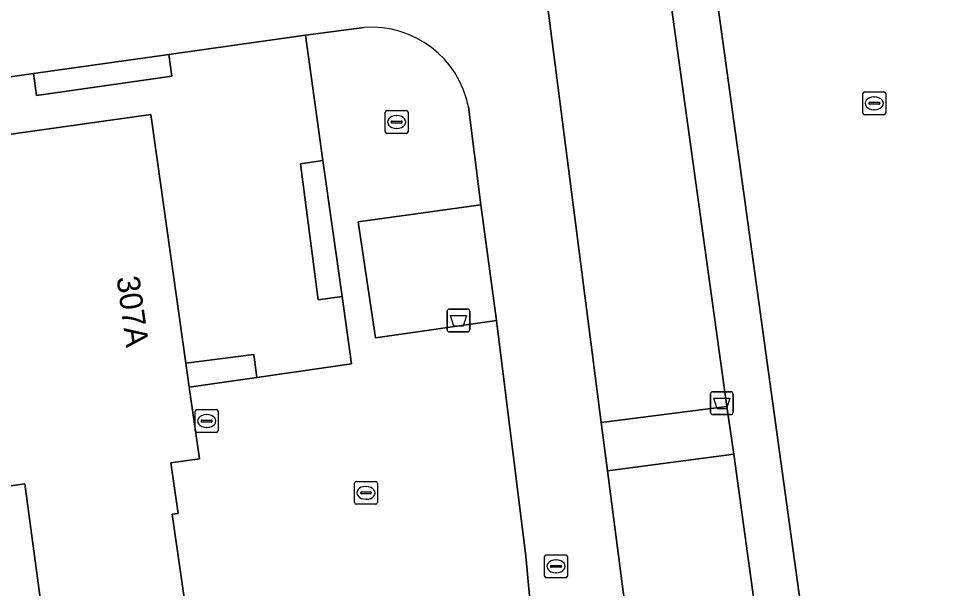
# Model space of a CAD drawing. Extents: x 162156 to 163172, y 378995 to 380779.
# Drawn here: x 162268.76 to 162309.86, y 379918.76 to 379943.7 of the extents above; entities that cross this region are included whole.
import ezdxf

# ---------------------------------------------------------------- set-up
doc = ezdxf.new("R2010")
doc.units = 0
for name, color, linetype in [('IMGEO_Afvalbak', 7, 'Continuous'), ('IMGEO_Brandkraan', 7, 'Continuous'), ('IMGEO_Groenvoorziening', 7, 'Continuous'), ('IMGEO_Kolk', 7, 'Continuous'), ('IMGEO_Pand', 7, 'Continuous'), ('IMGEO_Pand_nummerreeks', 7, 'Continuous'), ('IMGEO_Rioolput', 7, 'Continuous'), ('IMGEO_Terreindeel_open', 7, 'Continuous'), ('IMGEO_Voetpad_open', 7, 'Continuous'), ('IMGEO_Waterleidingput', 7, 'Continuous')]:
    doc.layers.add(name, color=color, linetype=linetype)

msp = doc.modelspace()

# ---------------------------------------------------------------- linework, layer by layer
at = {"layer": 'IMGEO_Afvalbak'}
for p, q in [((162287.621, 379930.992), (162288.411, 379930.992)), ((162288.411, 379930.992), (162287.621, 379930.992)), ((162287.521, 379930.092), (162287.521, 379930.892)), ((162287.521, 379930.892), (162287.521, 379930.092)), ((162288.511, 379930.892), (162288.511, 379930.092)), ((162288.511, 379930.092), (162288.511, 379930.892)), ((162288.411, 379929.992), (162287.621, 379929.992)), ((162287.621, 379929.992), (162288.411, 379929.992)), ((162299.153, 379927.37), (162299.943, 379927.37)), ((162299.943, 379927.37), (162299.153, 379927.37)), ((162299.053, 379926.47), (162299.053, 379927.27)), ((162299.053, 379927.27), (162299.053, 379926.47)), ((162300.043, 379927.27), (162300.043, 379926.47)), ((162300.043, 379926.47), (162300.043, 379927.27)), ((162299.943, 379926.37), (162299.153, 379926.37)), ((162299.153, 379926.37), (162299.943, 379926.37))]:
    msp.add_line(p, q, dxfattribs=at)
for points in [[(162287.664, 379930.706), (162288.368, 379930.706), (162288.219, 379930.236), (162287.813, 379930.236), (162287.664, 379930.706)], [(162299.196, 379927.084), (162299.9, 379927.084), (162299.751, 379926.614), (162299.345, 379926.614), (162299.196, 379927.084)]]:
    msp.add_lwpolyline(points, dxfattribs=at)
for centre, start, end in [((162287.621, 379930.892), 90, 180), ((162287.621, 379930.892), 90, 180), ((162288.411, 379930.892), 0, 90), ((162288.411, 379930.892), 360, 90), ((162287.621, 379930.092), 180, 270), ((162287.621, 379930.092), 180, 270), ((162288.411, 379930.092), 270, 0), ((162288.411, 379930.092), 270, 0), ((162299.153, 379927.27), 90, 180), ((162299.153, 379927.27), 90, 180), ((162299.943, 379927.27), 0, 90), ((162299.943, 379927.27), 360, 90), ((162299.153, 379926.47), 180, 270), ((162299.153, 379926.47), 180, 270), ((162299.943, 379926.47), 270, 0), ((162299.943, 379926.47), 270, 0)]:
    msp.add_arc(centre, 0.1, start, end, dxfattribs=at)
at = {"layer": 'IMGEO_Brandkraan'}
for p, q in [((162276.491, 379925.66), (162276.491, 379926.512)), ((162276.566, 379926.586), (162277.418, 379926.586)), ((162277.492, 379926.512), (162277.492, 379925.66)), ((162276.75, 379926.08), (162276.75, 379926.092)), ((162277.188, 379926.043), (162276.79, 379926.043)), ((162276.793, 379926.129), (162277.191, 379926.129)), ((162276.979, 379926.366), (162277.004, 379926.366)), ((162277.234, 379926.092), (162277.234, 379926.08)), ((162277.002, 379925.806), (162276.977, 379925.806)), ((162277.418, 379925.586), (162276.566, 379925.586))]:
    msp.add_line(p, q, dxfattribs=at)
for points in [[(162276.491, 379925.66), (162276.491, 379926.512)], [(162276.566, 379926.586), (162277.418, 379926.586)], [(162277.492, 379926.512), (162277.492, 379925.66)], [(162277.418, 379925.586), (162276.566, 379925.586)]]:
    msp.add_lwpolyline(points, dxfattribs=at)
for centre, radius, start, end in [((162276.568, 379926.51), 0.0765, 91.552, 178.448), ((162276.568, 379926.51), 0.0765, 91.552, 178.448), ((162277.416, 379926.51), 0.0765, 1.552, 88.448), ((162277.416, 379926.51), 0.0765, 1.552, 88.448), ((162276.79, 379926.089), 0.0403, 85.8775, 175.7526), ((162276.787, 379926.079), 0.0366, 178.938, 274.7102), ((162277.191, 379926.086), 0.043, 264.8664, 352.4533), ((162277.195, 379926.091), 0.0386, 1.7309, 96.639), ((162276.568, 379925.662), 0.0765, 181.552, 268.448), ((162276.568, 379925.662), 0.0765, 181.552, 268.448), ((162277.416, 379925.662), 0.0765, 271.552, 358.448), ((162277.416, 379925.662), 0.0765, 271.552, 358.448)]:
    msp.add_arc(centre, radius, start, end, dxfattribs=at)
for centre, major_axis, ratio, start_param, end_param in [((162276.978, 379926.086), (-0.387, 0.002), 0.722429, 4.712389, 7.853982), ((162277.003, 379926.086), (-0.39, 0.002), 0.717154, 1.570796, 4.712389)]:
    msp.add_ellipse(centre, major_axis=major_axis, ratio=ratio, start_param=start_param, end_param=end_param, dxfattribs=at)
at = {"layer": 'IMGEO_Groenvoorziening'}
for points in [[(162297.268, 379944.856), (162291.938, 379944.183), (162294.275, 379926.021), (162299.766, 379926.723)], [(162275.328, 379942.144), (162269.407, 379941.31), (162269.531, 379940.346), (162275.471, 379941.196)], [(162282.084, 379937.493), (162281.102, 379937.348), (162281.874, 379931.397), (162282.92, 379931.544)], [(162289.001, 379935.557), (162283.618, 379934.81), (162284.388, 379929.728), (162289.689, 379930.495)], [(162276.082, 379928.614), (162276.229, 379927.573), (162279.187, 379927.996), (162279.054, 379929.003)], [(162300.075, 379924.63), (162294.55, 379923.905), (162297.816, 379898.725), (162303.536, 379899.484)]]:
    msp.add_lwpolyline(points, close=True, dxfattribs=at)
at = {"layer": 'IMGEO_Kolk'}
for p, q in [((162284.811, 379938.756), (162284.811, 379939.608)), ((162284.886, 379939.682), (162285.738, 379939.682)), ((162285.812, 379939.608), (162285.812, 379938.756)), ((162285.113, 379939.225), (162285.511, 379939.225)), ((162285.299, 379939.462), (162285.324, 379939.462)), ((162285.07, 379939.176), (162285.07, 379939.188)), ((162285.508, 379939.139), (162285.11, 379939.139)), ((162285.322, 379938.902), (162285.297, 379938.902)), ((162285.554, 379939.188), (162285.554, 379939.176)), ((162285.738, 379938.682), (162284.886, 379938.682)), ((162283.468, 379922.515), (162283.468, 379923.367)), ((162283.543, 379923.441), (162284.395, 379923.441)), ((162283.956, 379923.221), (162283.981, 379923.221)), ((162284.469, 379923.367), (162284.469, 379922.515)), ((162283.727, 379922.935), (162283.727, 379922.947)), ((162284.165, 379922.898), (162283.767, 379922.898)), ((162283.77, 379922.984), (162284.168, 379922.984)), ((162284.211, 379922.947), (162284.211, 379922.935)), ((162284.395, 379922.441), (162283.543, 379922.441)), ((162283.979, 379922.661), (162283.954, 379922.661))]:
    msp.add_line(p, q, dxfattribs=at)
for points in [[(162284.811, 379938.756), (162284.811, 379939.608)], [(162284.886, 379939.682), (162285.738, 379939.682)], [(162285.812, 379939.608), (162285.812, 379938.756)], [(162285.738, 379938.682), (162284.886, 379938.682)], [(162283.468, 379922.515), (162283.468, 379923.367)], [(162283.543, 379923.441), (162284.395, 379923.441)], [(162284.469, 379923.367), (162284.469, 379922.515)], [(162284.395, 379922.441), (162283.543, 379922.441)]]:
    msp.add_lwpolyline(points, dxfattribs=at)
for centre, radius, start, end in [((162284.888, 379939.606), 0.0765, 91.552, 178.448), ((162284.888, 379939.606), 0.0765, 91.552, 178.448), ((162285.736, 379939.606), 0.0765, 1.552, 88.448), ((162285.736, 379939.606), 0.0765, 1.552, 88.448), ((162285.11, 379939.185), 0.0403, 85.8775, 175.7526), ((162285.515, 379939.187), 0.0386, 1.7309, 96.639), ((162285.107, 379939.175), 0.0366, 178.938, 274.7102), ((162285.511, 379939.182), 0.043, 264.8664, 352.4533), ((162284.888, 379938.758), 0.0765, 181.552, 268.448), ((162284.888, 379938.758), 0.0765, 181.552, 268.448), ((162285.736, 379938.758), 0.0765, 271.552, 358.448), ((162285.736, 379938.758), 0.0765, 271.552, 358.448), ((162283.545, 379923.365), 0.0765, 91.552, 178.448), ((162283.545, 379923.365), 0.0765, 91.552, 178.448), ((162284.393, 379923.365), 0.0765, 1.552, 88.448), ((162284.393, 379923.365), 0.0765, 1.552, 88.448), ((162283.767, 379922.944), 0.0403, 85.8775, 175.7526), ((162283.764, 379922.934), 0.0366, 178.938, 274.7102), ((162284.168, 379922.941), 0.043, 264.8664, 352.4533), ((162284.172, 379922.946), 0.0386, 1.7309, 96.639), ((162283.545, 379922.517), 0.0765, 181.552, 268.448), ((162283.545, 379922.517), 0.0765, 181.552, 268.448), ((162284.393, 379922.517), 0.0765, 271.552, 358.448), ((162284.393, 379922.517), 0.0765, 271.552, 358.448)]:
    msp.add_arc(centre, radius, start, end, dxfattribs=at)
for centre, major_axis, ratio, start_param, end_param in [((162285.298, 379939.182), (-0.387, 0.002), 0.722429, 4.712389, 7.853982), ((162285.323, 379939.182), (-0.39, 0.002), 0.717154, 1.570796, 4.712389), ((162283.955, 379922.941), (-0.387, 0.002), 0.722429, 4.712389, 7.853982), ((162283.98, 379922.941), (-0.39, 0.002), 0.717154, 1.570796, 4.712389)]:
    msp.add_ellipse(centre, major_axis=major_axis, ratio=ratio, start_param=start_param, end_param=end_param, dxfattribs=at)
at = {"layer": 'IMGEO_Pand'}
msp.add_lwpolyline([(162276.229, 379927.573), (162276.082, 379928.614), (162274.545, 379939.509), (162264.468, 379938.097), (162264.462, 379938.136), (162261.421, 379937.699), (162261.387, 379937.936), (162260.516, 379937.807), (162261.083, 379933.902), (162262.057, 379927.197), (162262.913, 379927.322), (162262.877, 379927.566), (162265.84, 379927.99), (162266.556, 379922.984), (162266.589, 379922.989), (162269.032, 379923.34), (162270.077, 379915.508), (162276.289, 379916.315), (162275.482, 379922.006), (162275.739, 379922.042), (162275.426, 379924.249), (162276.673, 379924.426)], close=True, dxfattribs=at)
at = {"layer": 'IMGEO_Rioolput'}
for p, q in [((162291.79, 379919.297), (162291.79, 379920.149)), ((162291.865, 379920.223), (162292.717, 379920.223)), ((162292.278, 379920.003), (162292.303, 379920.003)), ((162292.791, 379920.149), (162292.791, 379919.297)), ((162292.049, 379919.717), (162292.049, 379919.729)), ((162292.487, 379919.68), (162292.089, 379919.68)), ((162292.092, 379919.766), (162292.49, 379919.766)), ((162292.533, 379919.729), (162292.533, 379919.717)), ((162292.717, 379919.223), (162291.865, 379919.223)), ((162292.301, 379919.443), (162292.276, 379919.443))]:
    msp.add_line(p, q, dxfattribs=at)
for points in [[(162291.79, 379919.297), (162291.79, 379920.149)], [(162291.865, 379920.223), (162292.717, 379920.223)], [(162292.791, 379920.149), (162292.791, 379919.297)], [(162292.717, 379919.223), (162291.865, 379919.223)]]:
    msp.add_lwpolyline(points, dxfattribs=at)
for centre, radius, start, end in [((162291.867, 379920.147), 0.0765, 91.552, 178.448), ((162291.867, 379920.147), 0.0765, 91.552, 178.448), ((162292.715, 379920.147), 0.0765, 1.552, 88.448), ((162292.715, 379920.147), 0.0765, 1.552, 88.448), ((162292.089, 379919.726), 0.0403, 85.8775, 175.7526), ((162292.086, 379919.716), 0.0366, 178.938, 274.7102), ((162292.49, 379919.723), 0.043, 264.8664, 352.4533), ((162292.494, 379919.728), 0.0386, 1.7309, 96.639), ((162291.867, 379919.299), 0.0765, 181.552, 268.448), ((162291.867, 379919.299), 0.0765, 181.552, 268.448), ((162292.715, 379919.299), 0.0765, 271.552, 358.448), ((162292.715, 379919.299), 0.0765, 271.552, 358.448)]:
    msp.add_arc(centre, radius, start, end, dxfattribs=at)
for centre, major_axis, ratio, start_param, end_param in [((162292.277, 379919.723), (-0.387, 0.002), 0.722429, 4.712389, 7.853982), ((162292.302, 379919.723), (-0.39, 0.002), 0.717154, 1.570796, 4.712389)]:
    msp.add_ellipse(centre, major_axis=major_axis, ratio=ratio, start_param=start_param, end_param=end_param, dxfattribs=at)
at = {"layer": 'IMGEO_Terreindeel_open'}
msp.add_lwpolyline([(162369.608, 379954.625), (162368.912, 379959.951), (162298.57, 379950.126), (162313.201, 379844.187), (162383.496, 379853.919)], close=True, dxfattribs=at)
at = {"layer": 'IMGEO_Voetpad_open'}
for points in [[(162258.604, 379948.382), (162258.531, 379948.938), (162251.352, 380003.968), (162249.679, 380016.96), (162245.315, 380016.372), (162245.197, 380016.361), (162246.876, 380003.284), (162254.966, 379941.182), (162255.213, 379939.286), (162260.444, 379940.048), (162266.413, 379940.889), (162269.407, 379941.31), (162275.328, 379942.144), (162281.312, 379942.987), (162283.887, 379943.326)], [(162298.076, 379896.625), (162297.816, 379898.725), (162294.55, 379923.905), (162294.275, 379926.021), (162291.938, 379944.183), (162291.356, 379948.604), (162289.52, 379948.334), (162264.168, 379944.746), (162263.207, 379944.595)], [(162283.887, 379943.326), (162281.312, 379942.987), (162282.084, 379937.493), (162282.92, 379931.544), (162283.335, 379928.593), (162279.187, 379927.996), (162276.229, 379927.573), (162276.673, 379924.426), (162275.426, 379924.249), (162275.739, 379922.042), (162275.482, 379922.006), (162276.289, 379916.315), (162290.259, 379918.129), (162291.138, 379918.277), (162290.973, 379920.171), (162289.689, 379930.495)], [(162264.468, 379938.097), (162274.545, 379939.509), (162276.082, 379928.614), (162279.054, 379929.003), (162279.187, 379927.996), (162283.335, 379928.593), (162282.92, 379931.544), (162281.874, 379931.397), (162281.102, 379937.348), (162282.084, 379937.493), (162281.312, 379942.987), (162275.328, 379942.144), (162275.471, 379941.196), (162269.531, 379940.346), (162269.407, 379941.31), (162266.413, 379940.889)], [(162289.689, 379930.495), (162284.388, 379929.728), (162283.618, 379934.81), (162289.001, 379935.557), (162288.46, 379939.846)], [(162288.46, 379939.846), (162289.001, 379935.557), (162289.689, 379930.495), (162290.973, 379920.171), (162291.138, 379918.277), (162293.851, 379898.324), (162292.836, 379898.197), (162293.23, 379895.146), (162294.23, 379895.292), (162295.384, 379886.281), (162295.69, 379884.185), (162295.989, 379881.868), (162298.282, 379864.121), (162300.383, 379864.471), (162302.148, 379864.765), (162301.698, 379868.289), (162298.076, 379896.625)], [(162270.077, 379915.508), (162269.032, 379923.34), (162266.589, 379922.989)]]:
    msp.add_lwpolyline(points, dxfattribs=at)
for points in [[(162369.639, 379962.54), (162342.462, 379958.776), (162315.523, 379955.046), (162296.268, 379952.379), (162296.65, 379949.341), (162297.268, 379944.856), (162299.766, 379926.723), (162300.075, 379924.63), (162303.536, 379899.484), (162303.845, 379897.389), (162309.019, 379859.894), (162311.244, 379843.757), (162311.908, 379838.939), (162341.724, 379843.061), (162341.312, 379846.043), (162383.131, 379851.844), (162384.777, 379852.072), (162370.627, 379954.755)], [(162368.912, 379959.951), (162369.608, 379954.625), (162383.496, 379853.919), (162313.201, 379844.187), (162298.57, 379950.126)], [(162299.766, 379926.723), (162294.275, 379926.021), (162294.55, 379923.905), (162300.075, 379924.63)]]:
    msp.add_lwpolyline(points, close=True, dxfattribs=at)
msp.add_arc((162284.196, 379938.987), 4.35, 11.3888, 94.0697, dxfattribs=at)
msp.add_arc((162284.196, 379938.987), 4.35, 11.3888, 94.0697, dxfattribs=at)
at = {"layer": 'IMGEO_Waterleidingput'}
for p, q in [((162305.728, 379939.576), (162305.728, 379940.428)), ((162305.803, 379940.502), (162306.655, 379940.502)), ((162306.729, 379940.428), (162306.729, 379939.576)), ((162306.03, 379940.045), (162306.428, 379940.045)), ((162306.216, 379940.282), (162306.241, 379940.282)), ((162305.987, 379939.996), (162305.987, 379940.008)), ((162306.425, 379939.959), (162306.027, 379939.959)), ((162306.239, 379939.722), (162306.214, 379939.722)), ((162306.471, 379940.008), (162306.471, 379939.996)), ((162306.655, 379939.502), (162305.803, 379939.502))]:
    msp.add_line(p, q, dxfattribs=at)
for points in [[(162305.728, 379939.576), (162305.728, 379940.428)], [(162305.803, 379940.502), (162306.655, 379940.502)], [(162306.729, 379940.428), (162306.729, 379939.576)], [(162306.655, 379939.502), (162305.803, 379939.502)]]:
    msp.add_lwpolyline(points, dxfattribs=at)
for centre, radius, start, end in [((162305.805, 379940.426), 0.0765, 91.552, 178.448), ((162305.805, 379940.426), 0.0765, 91.552, 178.448), ((162306.653, 379940.426), 0.0765, 1.552, 88.448), ((162306.653, 379940.426), 0.0765, 1.552, 88.448), ((162306.027, 379940.005), 0.0403, 85.8775, 175.7526), ((162306.432, 379940.007), 0.0386, 1.7309, 96.639), ((162306.024, 379939.995), 0.0366, 178.938, 274.7102), ((162306.428, 379940.002), 0.043, 264.8664, 352.4533), ((162305.805, 379939.578), 0.0765, 181.552, 268.448), ((162305.805, 379939.578), 0.0765, 181.552, 268.448), ((162306.653, 379939.578), 0.0765, 271.552, 358.448), ((162306.653, 379939.578), 0.0765, 271.552, 358.448)]:
    msp.add_arc(centre, radius, start, end, dxfattribs=at)
for centre, major_axis, ratio, start_param, end_param in [((162306.215, 379940.002), (-0.387, 0.002), 0.722429, 4.712389, 7.853982), ((162306.24, 379940.002), (-0.39, 0.002), 0.717154, 1.570796, 4.712389)]:
    msp.add_ellipse(centre, major_axis=major_axis, ratio=ratio, start_param=start_param, end_param=end_param, dxfattribs=at)

# ---------------------------------------------------------------- texts
at = {"layer": 'IMGEO_Pand_nummerreeks'}
msp.add_text('307A', height=1, rotation=278.0155, dxfattribs=at).set_placement((162273.038, 379932.37))

doc.saveas('drawing.dxf')
